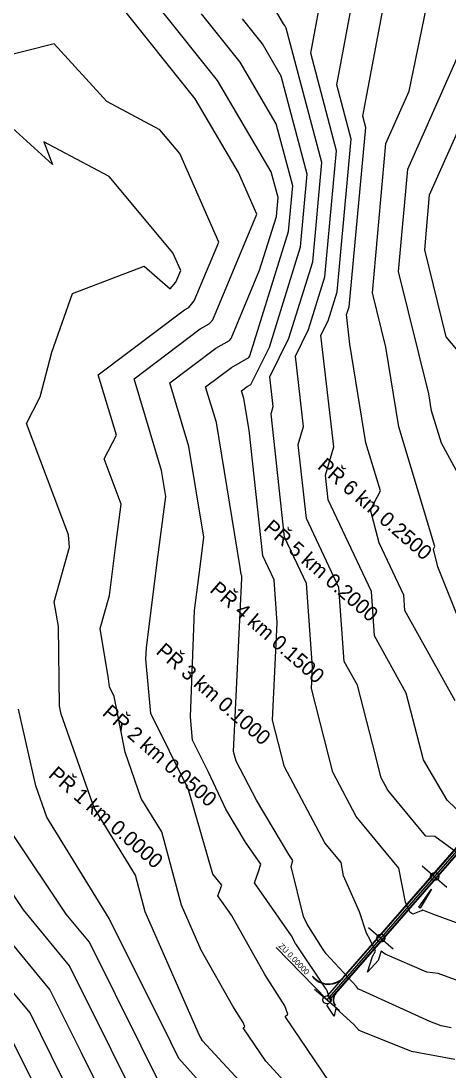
# Model space of a CAD drawing. Extents: x -549394 to -546608, y -1037055 to -1033629.
# Drawn here: x -548396 to -548134, y -1035101 to -1034460 of the extents above; entities that cross this region are included whole.
import ezdxf

# ---------------------------------------------------------------- set-up
doc = ezdxf.new("R2010")
doc.units = 0
for name, color, linetype in [('hlavni_vrst', 7, 'Continuous'), ('norm_vrst', 7, 'Continuous'), ('POLYGONY_SITUACE_PO', 7, 'Continuous'), ('u_sirka_1_0m', 7, 'Continuous'), ('x_navrh_C121', 7, 'Continuous'), ('x_osa_C121', 7, 'Continuous'), ('x_popis_oblouky_C121', 7, 'Continuous'), ('x_popis_pricne_rezy_C121', 7, 'Continuous')]:
    doc.layers.add(name, color=color, linetype=linetype)

msp = doc.modelspace()

# ---------------------------------------------------------------- linework, layer by layer
at = {"layer": 'hlavni_vrst'}
for p, q in [((-548158.61, -1034502.63), (-548146.08, -1034442.45)), ((-548248.12, -1034473.83), (-548260.31, -1034458.52)), ((-548236.61, -1034493.43), (-548248.12, -1034473.83)), ((-548220.73, -1034553.48), (-548236.61, -1034493.43)), ((-548172.84, -1034534.63), (-548158.61, -1034502.63)), ((-548376.25, -1034547.47), (-548416.66, -1034510.84)), ((-548381.57, -1034533.57), (-548376.25, -1034547.47)), ((-548341.67, -1034554.86), (-548381.57, -1034533.57)), ((-548181.01, -1034626.04), (-548172.84, -1034534.63)), ((-548302.78, -1034601.44), (-548341.67, -1034554.86)), ((-548224.81, -1034597.75), (-548220.73, -1034553.48)), ((-548298.02, -1034612.3), (-548302.78, -1034601.44)), ((-548243.89, -1034659.08), (-548224.81, -1034597.75)), ((-548364.17, -1034626.36), (-548320.4, -1034609.68)), ((-548320.4, -1034609.68), (-548304.49, -1034623.49)), ((-548301, -1034619.47), (-548298.02, -1034612.3)), ((-548304.49, -1034623.49), (-548301, -1034619.47)), ((-548376.8, -1034662.17), (-548364.17, -1034626.36)), ((-548172.85, -1034659.09), (-548181.01, -1034626.04)), ((-548255.14, -1034681.89), (-548243.89, -1034659.08)), ((-548164.9, -1034707.86), (-548172.85, -1034659.09)), ((-548383.78, -1034689.57), (-548376.8, -1034662.17)), ((-548260.92, -1034685.79), (-548257.48, -1034683.19)), ((-548257.48, -1034683.19), (-548255.14, -1034681.89)), ((-548392.2, -1034705.88), (-548383.78, -1034689.57)), ((-548259.49, -1034690.57), (-548260.92, -1034685.79)), ((-548256.29, -1034709.94), (-548259.49, -1034690.57)), ((-548379.35, -1034739.81), (-548392.2, -1034705.88)), ((-548247.86, -1034786.65), (-548256.29, -1034709.94)), ((-548142.85, -1034780.89), (-548164.9, -1034707.86)), ((-548366.57, -1034773.82), (-548379.35, -1034739.81)), ((-548365.91, -1034781.32), (-548366.57, -1034773.82)), ((-548375.22, -1034814.79), (-548365.91, -1034781.32)), ((-548143.73, -1034782.59), (-548142.85, -1034780.89)), ((-548240.98, -1034801.29), (-548247.86, -1034786.65)), ((-548140.96, -1034793.3), (-548143.73, -1034782.59)), ((-548129.19, -1034823), (-548140.96, -1034793.3)), ((-548239.11, -1034827.58), (-548240.98, -1034801.29)), ((-548372.7, -1034829.89), (-548375.22, -1034814.79)), ((-548372.03, -1034878.25), (-548372.7, -1034829.89)), ((-548241.98, -1034887.04), (-548239.11, -1034827.58)), ((-548371.03, -1034883.34), (-548372.03, -1034878.25)), ((-548350.92, -1034940.67), (-548371.03, -1034883.34)), ((-548234.71, -1034915.58), (-548241.98, -1034887.04)), ((-548210.1, -1034962.11), (-548234.71, -1034915.58)), ((-548325.66, -1034981.81), (-548350.92, -1034940.67)), ((-548200.15, -1034974.14), (-548210.1, -1034962.11)), ((-548198.58, -1034982.16), (-548200.15, -1034974.14)), ((-548319.63, -1035004.27), (-548325.66, -1034981.81)), ((-548188.85, -1035004.3), (-548198.58, -1034982.16)), ((-548390, -1035066.03), (-548446.34, -1034997.78)), ((-548286.55, -1035079.75), (-548319.63, -1035004.27)), ((-548184.56, -1035017.32), (-548188.85, -1035004.3)), ((-548182.4, -1035021.26), (-548184.56, -1035017.32)), ((-548179.09, -1035028.24), (-548182.4, -1035021.26)), ((-548184.04, -1035041.05), (-548180.87, -1035031.46)), ((-548180.87, -1035031.46), (-548179.09, -1035028.24)), ((-548175.69, -1035028.31), (-548177.55, -1035033.94)), ((-548173.24, -1035030), (-548175.69, -1035028.31)), ((-548147.84, -1035041.1), (-548173.24, -1035030)), ((-548177.55, -1035033.94), (-548184.04, -1035041.05)), ((-548140.91, -1035041.86), (-548147.84, -1035041.1)), ((-548113.62, -1035051.86), (-548140.91, -1035041.86)), ((-548376.85, -1035092.43), (-548390, -1035066.03)), ((-548285.63, -1035081.39), (-548286.55, -1035079.75)), ((-548285.33, -1035081.86), (-548285.63, -1035081.39)), ((-548285.28, -1035081.98), (-548285.33, -1035081.86)), ((-548285.32, -1035082.01), (-548285.28, -1035081.98)), ((-548284.67, -1035082.98), (-548285.32, -1035082.01)), ((-548236.21, -1035135.54), (-548284.67, -1035082.98)), ((-548351.89, -1035142.66), (-548376.85, -1035092.43))]:
    msp.add_line(p, q, dxfattribs=at)
at = {"layer": 'norm_vrst'}
for p, q in [((-548186.88, -1034518.02), (-548169.38, -1034425.17)), ((-548202.78, -1034498.76), (-548190.3, -1034432.56)), ((-548218.68, -1034479.5), (-548212.7, -1034447.78)), ((-548289.24, -1034507.32), (-548335.3, -1034449.47)), ((-548275.53, -1034496.16), (-548310.3, -1034452.49)), ((-548235.31, -1034461.54), (-548240.14, -1034453.28)), ((-548261.82, -1034485), (-548285.31, -1034455.5)), ((-548234.41, -1034462.67), (-548235.31, -1034461.54)), ((-548233.55, -1034464.12), (-548234.41, -1034462.67)), ((-548211.81, -1034546.33), (-548233.55, -1034464.12)), ((-548375.32, -1034473.87), (-548422.06, -1034485.46)), ((-548343.1, -1034509.02), (-548375.32, -1034473.87)), ((-548202.9, -1034539.18), (-548218.68, -1034479.5)), ((-548159.45, -1034550.3), (-548125.98, -1034475.07)), ((-548239.67, -1034522.74), (-548261.82, -1034485)), ((-548242.72, -1034552.04), (-548275.53, -1034496.16)), ((-548193.98, -1034532.04), (-548202.78, -1034498.76)), ((-548310.71, -1034526.31), (-548343.1, -1034509.02)), ((-548262.8, -1034552.35), (-548289.24, -1034507.32)), ((-548185.07, -1034524.89), (-548186.88, -1034518.02)), ((-548146.06, -1034565.97), (-548124.79, -1034518.16)), ((-548229.64, -1034560.63), (-548239.67, -1034522.74)), ((-548195.18, -1034634.51), (-548185.07, -1034524.89)), ((-548298.64, -1034540.76), (-548310.71, -1034526.31)), ((-548202.58, -1034625.32), (-548193.98, -1034532.04)), ((-548274.82, -1034595.07), (-548298.64, -1034540.76)), ((-548209.99, -1034616.13), (-548202.9, -1034539.18)), ((-548217.4, -1034606.94), (-548211.81, -1034546.33)), ((-548165.04, -1034612.88), (-548159.45, -1034550.3)), ((-548251.62, -1034577.85), (-548262.8, -1034552.35)), ((-548238.56, -1034567.78), (-548242.72, -1034552.04)), ((-548232.22, -1034588.56), (-548229.64, -1034560.63)), ((-548239.63, -1034579.37), (-548238.56, -1034567.78)), ((-548149.08, -1034599.71), (-548146.06, -1034565.97)), ((-548278.43, -1034642.39), (-548251.62, -1034577.85)), ((-548249.83, -1034612.15), (-548239.63, -1034579.37)), ((-548255.83, -1034664.46), (-548232.22, -1034588.56)), ((-548289.72, -1034630.93), (-548274.82, -1034595.07)), ((-548135.97, -1034652.77), (-548149.08, -1034599.71)), ((-548231.95, -1034653.7), (-548217.4, -1034606.94)), ((-548267.15, -1034653.85), (-548249.83, -1034612.15)), ((-548146.55, -1034687.75), (-548165.04, -1034612.88)), ((-548220.01, -1034648.33), (-548209.99, -1034616.13)), ((-548208.07, -1034642.95), (-548202.58, -1034625.32)), ((-548293.11, -1034634.84), (-548289.72, -1034630.93)), ((-548348.38, -1034676.06), (-548295.78, -1034636.32)), ((-548295.78, -1034636.32), (-548293.11, -1034634.84)), ((-548196.89, -1034639.11), (-548196.13, -1034637.57)), ((-548194.75, -1034657.36), (-548196.89, -1034639.11)), ((-548196.13, -1034637.57), (-548195.18, -1034634.51)), ((-548286.2, -1034648.04), (-548280.68, -1034644.97)), ((-548280.68, -1034644.97), (-548278.43, -1034642.39)), ((-548212.46, -1034651.84), (-548208.07, -1034642.95)), ((-548326.51, -1034678.49), (-548286.2, -1034648.04)), ((-548243.59, -1034677.3), (-548231.95, -1034653.7)), ((-548228.02, -1034664.57), (-548220.01, -1034648.33)), ((-548204.47, -1034720.05), (-548212.46, -1034651.84)), ((-548116.13, -1034676.43), (-548135.97, -1034652.77)), ((-548304.65, -1034680.92), (-548276.63, -1034659.75)), ((-548276.63, -1034659.75), (-548268.24, -1034655.11)), ((-548268.24, -1034655.11), (-548267.15, -1034653.85)), ((-548184.93, -1034717.6), (-548194.75, -1034657.36)), ((-548267.05, -1034671.47), (-548256.37, -1034665.55)), ((-548256.37, -1034665.55), (-548255.83, -1034664.46)), ((-548222.97, -1034707.7), (-548228.02, -1034664.57)), ((-548282.79, -1034683.36), (-548267.05, -1034671.47)), ((-548337.32, -1034712.91), (-548348.38, -1034676.06)), ((-548309.7, -1034734.52), (-548326.51, -1034678.49)), ((-548241.48, -1034695.36), (-548243.59, -1034677.3)), ((-548292.97, -1034719.87), (-548304.65, -1034680.92)), ((-548276.23, -1034705.22), (-548282.79, -1034683.36)), ((-548144.86, -1034698.12), (-548146.55, -1034687.75)), ((-548242.85, -1034699.92), (-548241.48, -1034695.36)), ((-548138.9, -1034717.87), (-548144.86, -1034698.12)), ((-548234.57, -1034775.21), (-548242.85, -1034699.92)), ((-548261.63, -1034793.74), (-548276.23, -1034705.22)), ((-548226.24, -1034718.6), (-548222.97, -1034707.7)), ((-548344.83, -1034727.44), (-548337.32, -1034712.91)), ((-548176.09, -1034746.9), (-548184.93, -1034717.6)), ((-548283.82, -1034775.31), (-548292.97, -1034719.87)), ((-548221.28, -1034763.77), (-548226.24, -1034718.6)), ((-548209.64, -1034737.28), (-548204.47, -1034720.05)), ((-548109.97, -1034770.99), (-548138.9, -1034717.87)), ((-548334.33, -1034755.14), (-548344.83, -1034727.44)), ((-548307.09, -1034750.36), (-548309.7, -1034734.52)), ((-548207.99, -1034752.34), (-548209.64, -1034737.28)), ((-548182.14, -1034758.61), (-548176.09, -1034746.9)), ((-548337.87, -1034781.62), (-548334.33, -1034755.14)), ((-548312.05, -1034787.45), (-548307.09, -1034750.36)), ((-548181.64, -1034808.42), (-548207.99, -1034752.34)), ((-548176.94, -1034778.68), (-548182.14, -1034758.61)), ((-548201.42, -1034806.04), (-548221.28, -1034763.77)), ((-548286.22, -1034793.29), (-548283.82, -1034775.31)), ((-548221.2, -1034803.67), (-548234.57, -1034775.21)), ((-548341.52, -1034810.82), (-548337.87, -1034781.62)), ((-548161.86, -1034810.79), (-548176.94, -1034778.68)), ((-548318.96, -1034842.78), (-548312.05, -1034787.45)), ((-548289.58, -1034820.09), (-548286.22, -1034793.29)), ((-548261.15, -1034798.08), (-548261.63, -1034793.74)), ((-548265.76, -1034906.31), (-548260.66, -1034800.4)), ((-548260.76, -1034798.91), (-548261.15, -1034798.08)), ((-548260.66, -1034800.4), (-548260.76, -1034798.91)), ((-548217.57, -1034854.76), (-548221.2, -1034803.67)), ((-548198.21, -1034851.18), (-548201.42, -1034806.04)), ((-548347.17, -1034831.13), (-548341.52, -1034810.82)), ((-548179.7, -1034835.65), (-548181.64, -1034808.42)), ((-548161.19, -1034820.11), (-548161.86, -1034810.79)), ((-548292.05, -1034885.13), (-548289.58, -1034820.09)), ((-548130.56, -1034875.29), (-548161.19, -1034820.11)), ((-548342.03, -1034861.93), (-548347.17, -1034831.13)), ((-548160.33, -1034870.54), (-548179.7, -1034835.65)), ((-548319.23, -1034849.75), (-548318.96, -1034842.78)), ((-548316.17, -1034883.06), (-548319.23, -1034849.75)), ((-548190.1, -1034865.79), (-548198.21, -1034851.18)), ((-548218.2, -1034867.77), (-548217.57, -1034854.76)), ((-548341.58, -1034866.81), (-548342.03, -1034861.93)), ((-548338.72, -1034872.64), (-548341.58, -1034866.81)), ((-548205.16, -1034918.95), (-548218.2, -1034867.77)), ((-548180.76, -1034902.12), (-548190.1, -1034865.79)), ((-548149.83, -1034911.36), (-548160.33, -1034870.54)), ((-548332.02, -1034906.58), (-548338.72, -1034872.64)), ((-548386.51, -1034927.14), (-548396.99, -1034880.35)), ((-548293.55, -1034929.15), (-548316.17, -1034883.06)), ((-548290.75, -1034899.3), (-548292.05, -1034885.13)), ((-548281.13, -1034918.9), (-548290.75, -1034899.3)), ((-548175.6, -1034922.33), (-548180.76, -1034902.12)), ((-548322.07, -1034934.95), (-548332.02, -1034906.58)), ((-548264.26, -1034912.2), (-548265.76, -1034906.31)), ((-548251.67, -1034936.01), (-548264.26, -1034912.2)), ((-548135.34, -1034935.88), (-548149.83, -1034911.36)), ((-548270.4, -1034941.39), (-548281.13, -1034918.9)), ((-548190.85, -1034946.02), (-548205.16, -1034918.95)), ((-548171.59, -1034929.93), (-548175.6, -1034922.33)), ((-548379.76, -1034946.38), (-548386.51, -1034927.14)), ((-548292.99, -1034930.32), (-548293.55, -1034929.15)), ((-548309.57, -1034955.32), (-548322.07, -1034934.95)), ((-548278.35, -1034981.13), (-548292.99, -1034930.32)), ((-548148.41, -1034957.93), (-548171.59, -1034929.93)), ((-548258.44, -1034961.64), (-548270.4, -1034941.39)), ((-548232.06, -1034969.21), (-548251.67, -1034936.01)), ((-548115.98, -1034954.78), (-548135.34, -1034935.88)), ((-548341.75, -1035008.31), (-548379.76, -1034946.38)), ((-548164.85, -1034977.44), (-548190.85, -1034946.02)), ((-548367.9, -1035005.68), (-548401.52, -1034955.28)), ((-548297.51, -1035000.24), (-548309.57, -1034955.32)), ((-548142.91, -1034958.09), (-548148.41, -1034957.93)), ((-548127.88, -1034969.1), (-548142.91, -1034958.09)), ((-548394.04, -1035003.04), (-548418.56, -1034966.31)), ((-548249.2, -1034975.11), (-548258.44, -1034961.64)), ((-548229.52, -1034972.92), (-548232.06, -1034969.21)), ((-548230.55, -1034976.55), (-548229.52, -1034972.92)), ((-548252.94, -1034986.52), (-548250.47, -1034979.54)), ((-548250.47, -1034979.54), (-548249.2, -1034975.11)), ((-548223.12, -1035007.15), (-548230.55, -1034976.55)), ((-548160.75, -1034998.41), (-548164.85, -1034977.44)), ((-548272.98, -1034987.99), (-548278.35, -1034981.13)), ((-548230.34, -1035018.92), (-548252.94, -1034986.52)), ((-548275.29, -1034994.5), (-548272.98, -1034987.99)), ((-548152.72, -1035001.43), (-548144.97, -1034990.32)), ((-548144.97, -1034990.32), (-548151.83, -1035002.04)), ((-548267.08, -1035006.27), (-548275.29, -1034994.5)), ((-548158.12, -1035004.39), (-548160.75, -1034998.41)), ((-548377.94, -1035051.6), (-548420.19, -1035000.41)), ((-548365.87, -1035037.17), (-548394.04, -1035003.04)), ((-548353.81, -1035022.74), (-548367.9, -1035005.68)), ((-548285.5, -1035027.64), (-548297.51, -1035000.24)), ((-548246.66, -1035042.42), (-548267.08, -1035006.27)), ((-548156.32, -1035005.56), (-548158.12, -1035004.39)), ((-548151.28, -1035003.53), (-548156.32, -1035005.56)), ((-548151.83, -1035002.04), (-548152.72, -1035001.43)), ((-548150.87, -1035003.8), (-548151.28, -1035003.53)), ((-548150.53, -1035003.22), (-548150.87, -1035003.8)), ((-548150.23, -1035003.21), (-548150.53, -1035003.22)), ((-548144.1, -1035005.61), (-548150.23, -1035003.21)), ((-548085.32, -1035027.15), (-548144.1, -1035005.61)), ((-548341.75, -1035008.31), (-548341.75, -1035008.31)), ((-548303.92, -1035084.29), (-548341.75, -1035008.31)), ((-548341.75, -1035008.31), (-548341.75, -1035008.31)), ((-548341.75, -1035008.31), (-548341.75, -1035008.31)), ((-548341.75, -1035008.31), (-548341.75, -1035008.31)), ((-548220.78, -1035011.77), (-548223.12, -1035007.15)), ((-548211.54, -1035026.58), (-548220.78, -1035011.77)), ((-548228.03, -1035023.48), (-548230.34, -1035018.92)), ((-548322.15, -1035086.33), (-548353.81, -1035022.74)), ((-548227.43, -1035024.45), (-548228.03, -1035023.48)), ((-548209.24, -1035051.53), (-548227.43, -1035024.45)), ((-548266.14, -1035061.9), (-548285.5, -1035027.64)), ((-548209.31, -1035029.91), (-548211.54, -1035026.58)), ((-548190.65, -1035049.83), (-548209.31, -1035029.91)), ((-548340.39, -1035088.36), (-548365.87, -1035037.17)), ((-548234.43, -1035061.72), (-548246.66, -1035042.42)), ((-548190.85, -1035049.89), (-548190.65, -1035049.83)), ((-548190.6, -1035050.34), (-548190.85, -1035049.89)), ((-548190.33, -1035050.52), (-548190.6, -1035050.34)), ((-548189.76, -1035051.65), (-548190.33, -1035050.52)), ((-548358.62, -1035090.4), (-548377.94, -1035051.6)), ((-548209.06, -1035051.73), (-548209.24, -1035051.53)), ((-548208.83, -1035052.15), (-548209.06, -1035051.73)), ((-548209.06, -1035051.73), (-548209.06, -1035051.73)), ((-548208.64, -1035052.6), (-548208.83, -1035052.15)), ((-548206.31, -1035059.06), (-548208.64, -1035052.6)), ((-548189.69, -1035051.4), (-548189.76, -1035051.65)), ((-548189.33, -1035051.47), (-548189.69, -1035051.4)), ((-548145.92, -1035071.14), (-548189.33, -1035051.47)), ((-548259.88, -1035071.79), (-548266.14, -1035061.9)), ((-548232.64, -1035066.7), (-548234.43, -1035061.72)), ((-548208.8, -1035061.28), (-548206.31, -1035059.06)), ((-548204.27, -1035068), (-548208.8, -1035061.28)), ((-548203.26, -1035063.01), (-548204.27, -1035068)), ((-548192.4, -1035072.99), (-548203.26, -1035063.01)), ((-548234.31, -1035068.19), (-548232.64, -1035066.7)), ((-548207.48, -1035107.98), (-548234.31, -1035068.19)), ((-548258.96, -1035074.34), (-548259.88, -1035071.79)), ((-548259.82, -1035075.1), (-548258.96, -1035074.34)), ((-548246.07, -1035095.48), (-548259.82, -1035075.1)), ((-548189.04, -1035076.69), (-548192.4, -1035072.99)), ((-548188.86, -1035076.72), (-548189.04, -1035076.69)), ((-548188.01, -1035077.11), (-548188.86, -1035076.72)), ((-548138.99, -1035073.95), (-548145.92, -1035071.14)), ((-548133, -1035075.05), (-548138.99, -1035073.95)), ((-548395.09, -1035094.47), (-548402.06, -1035080.46)), ((-548157.19, -1035089.62), (-548188.01, -1035077.11)), ((-548325.51, -1035118.29), (-548340.39, -1035088.36)), ((-548312.32, -1035106.11), (-548322.15, -1035086.33)), ((-548299.13, -1035093.93), (-548303.92, -1035084.29)), ((-548130.57, -1035094.51), (-548157.19, -1035089.62)), ((-548365.08, -1035154.84), (-548395.09, -1035094.47)), ((-548338.7, -1035130.48), (-548358.62, -1035090.4)), ((-548254.8, -1035142.92), (-548299.13, -1035093.93)), ((-548221.72, -1035121.89), (-548246.07, -1035095.48))]:
    msp.add_line(p, q, dxfattribs=at)
at = {"layer": 'POLYGONY_SITUACE_PO'}
msp.add_circle((-548208.71, -1035057.99), 2.5, dxfattribs=at)
at = {"layer": 'u_sirka_1_0m'}
for centre in [(-548143.02, -1034982.6), (-548175.87, -1035020.3)]:
    msp.add_circle(centre, 2.5, dxfattribs=at)
at = {"layer": 'x_navrh_C121'}
for p, q in [((-548208.33, -1035055.65), (-548022.55, -1034842.45)), ((-548206.76, -1035057.65), (-548020.66, -1034844.09))]:
    msp.add_line(p, q, dxfattribs=at)
for points in [[(-548198.55, -1035044.05), (-548022.74, -1034842.28)], [(-548203.31, -1035054.08), (-548027.05, -1034851.8)]]:
    msp.add_lwpolyline(points, dxfattribs=at)
for centre, radius, start, end in [((-548207.79, -1035036), 12.5, 217.82833, 318.93123), ((-548207.79, -1035036), 12.25, 217.82833, 318.93123), ((-548198.98, -1035057.86), 6, 138.93123, 218.05249), ((-548198.98, -1035057.86), 5.75, 138.93123, 218.05249)]:
    msp.add_arc(centre, radius, start, end, dxfattribs=at)
at = {"layer": 'x_osa_C121'}
msp.add_lwpolyline([(-548208.71, -1035057.99), (-548015.16, -1034835.88)], dxfattribs=at)
at = {"layer": 'x_popis_oblouky_C121'}
msp.add_lwpolyline([(-548239.68, -1035025.93), (-548208.71, -1035057.99)], dxfattribs=at)
at = {"layer": 'x_popis_pricne_rezy_C121'}
for points in [[(-548150.56, -1034976.03), (-548143.02, -1034982.6), (-548135.48, -1034989.17)], [(-548183.4, -1035013.73), (-548175.87, -1035020.3), (-548168.33, -1035026.87)], [(-548216.25, -1035051.42), (-548208.71, -1035057.99), (-548201.17, -1035064.56)]]:
    msp.add_lwpolyline(points, dxfattribs=at)

# ---------------------------------------------------------------- texts
at = {"layer": 'x_popis_oblouky_C121'}
msp.add_text('ZÚ 0.00000', height=3.5, rotation=314.00705, dxfattribs=at).set_placement((-548238.58, -1035025.4))
at = {"layer": 'x_popis_pricne_rezy_C121'}
for s, p in [('PŘ 6 km 0.2500', (-548215.11, -1034732.84)), ('PŘ 5 km 0.2000', (-548247.96, -1034770.53)), ('PŘ 4 km 0.1500', (-548280.81, -1034808.23)), ('PŘ 3 km 0.1000', (-548313.66, -1034845.92)), ('PŘ 2 km 0.0500', (-548346.51, -1034883.62)), ('PŘ 1 km 0.0000', (-548379.36, -1034921.32))]:
    msp.add_text(s, height=9.0627, rotation=318.93123, dxfattribs=at).set_placement(p)

doc.saveas('drawing.dxf')
